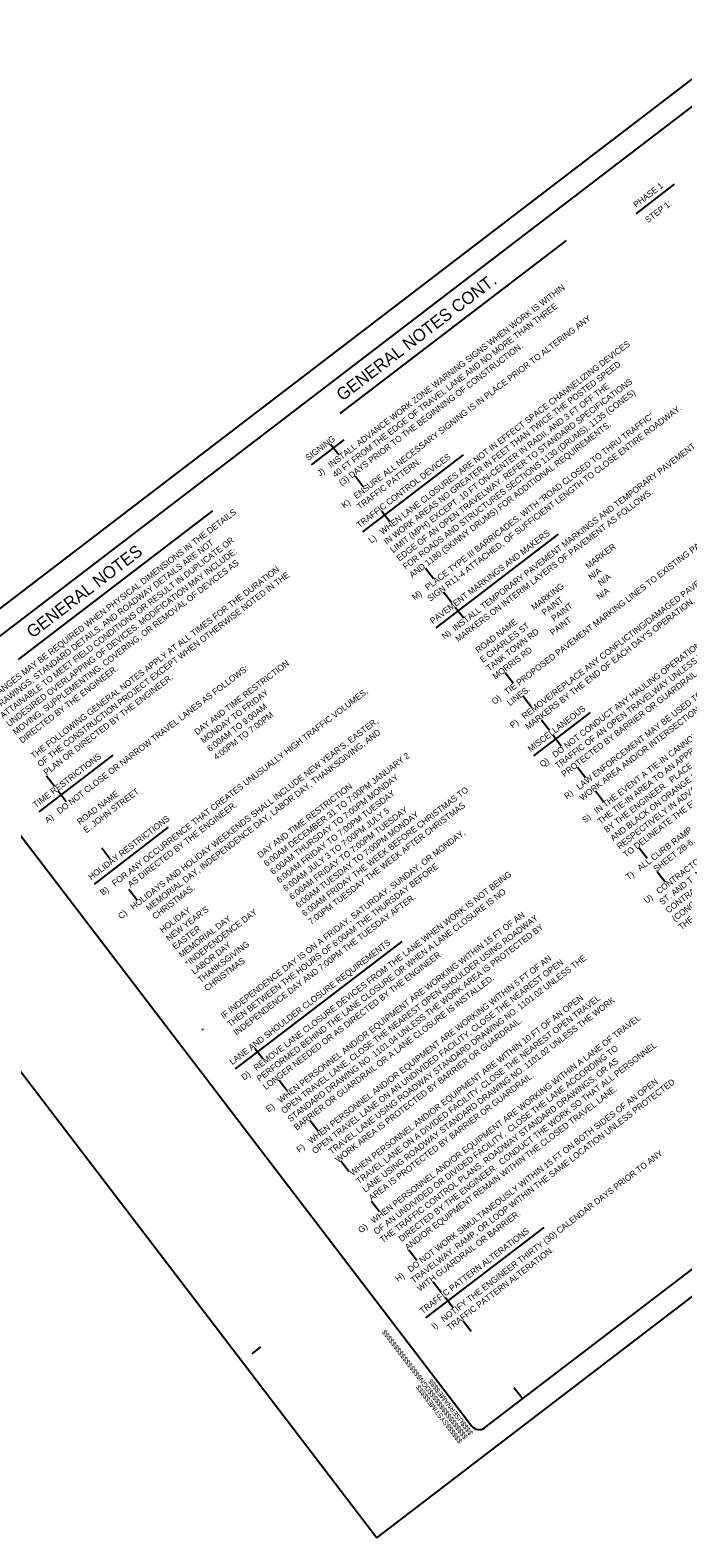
# Model space of a CAD drawing. Extents: x -606 to 2396, y -305 to 3662.
# Drawn here: x 269 to 1012, y 50 to 1764 of the extents above; entities that cross this region are included whole.
import ezdxf

# ---------------------------------------------------------------- set-up
doc = ezdxf.new("R2010")
doc.units = 0
for name, color, linetype in [('DEV BORDER CELL', 7, 'Continuous'), ('DEV TRANSPORTATION OPERATIONS PLAN SHEET', 7, 'Continuous'), ('Scratch_Level_4', 7, 'Continuous'), ('Sheet Plot Border Outside CELL', 7, 'Continuous'), ('Text', 7, 'Continuous')]:
    doc.layers.add(name, color=color, linetype=linetype)

msp = doc.modelspace()

# ---------------------------------------------------------------- linework, layer by layer
at = {"layer": 'DEV BORDER CELL'}
for p, q in [((1323.5, 1908.3), (148.3, 1009.6)), ((621.7, 1328.6), (879.1, 1525.5)), ((256.1, 1049), (476.9, 1217.9)), ((786.1, 175.5), (1961.3, 1074.2)), ((146.4, 995.2), (771.7, 177.5)), ((521.8, 259.8), (531.7, 267.4)), ((777.9, 169.3), (777.9, 169.3))]:
    msp.add_line(p, q, dxfattribs=at)
msp.add_arc((779.9, 183.7), 10.3, 217.404, 307.404, dxfattribs=at)
at = {"layer": 'Scratch_Level_4'}
for p, q in [((610.9, 1293.9), (620.1, 1282)), ((638.8, 1257.6), (647.9, 1245.6)), ((669.3, 1217.6), (678.4, 1205.7)), ((718.8, 1152.9), (727.9, 1141)), ((739.4, 1126), (748.5, 1114.1)), ((752.7, 1108.5), (761.9, 1096.6)), ((809.5, 1034.3), (818.6, 1022.4)), ((830.1, 1007.4), (839.2, 995.5)), ((850.7, 980.4), (859.8, 968.5)), ((864, 963), (873.1, 951)), ((891.8, 926.6), (901, 914.7)), ((287.8, 916.9), (296.9, 905)), ((301.1, 899.5), (310.3, 887.5)), ((912.4, 899.7), (921.5, 887.7)), ((350.7, 834.7), (359.8, 822.8)), ((961.9, 834.9), (971.1, 823)), ((982.5, 808), (991.6, 796.1)), ((381.4, 787.9), (390.5, 776)), ((524.6, 607.2), (533.8, 595.3)), ((552.5, 570.8), (561.6, 558.9)), ((587.5, 525), (596.6, 513)), ((622.6, 479.1), (631.7, 467.2)), ((657.6, 433.3), (666.7, 421.4)), ((699.9, 378), (709, 366.1)), ((727.7, 341.6), (736.8, 329.7)), ((741.1, 324.1), (750.2, 312.2)), ((761.7, 297.2), (770.8, 285.3)), ((819.5, 221.5), (828.7, 209.6))]:
    msp.add_line(p, q, dxfattribs=at)
at = {"layer": 'Sheet Plot Border Outside CELL'}
msp.add_lwpolyline([(663.6, 50.4), (2004.5, 1075.8), (1336.4, 1949.6), (-4.5, 924.2)], close=True, dxfattribs=at)
at = {"layer": 'Text'}
for p, q in [((958.3, 1555.6), (1002.2, 1589.2)), ((589.1, 1270.4), (626.3, 1298.8)), ((647.5, 1194.1), (761.9, 1281.5)), ((730.9, 1084.9), (870.3, 1191.5)), ((842.2, 939.4), (906.6, 988.6)), ((279.4, 875.9), (363.7, 940.4)), ((342.2, 793.7), (426.6, 858.2)), ((502.9, 583.6), (692.3, 728.5)), ((719.3, 300.6), (853.7, 403.3))]:
    msp.add_line(p, q, dxfattribs=at)

# ---------------------------------------------------------------- texts
at = {"layer": 'DEV BORDER CELL'}
for s, p in [('$$$$$$$$$$$$$$$$DGN$$$$$$$$$$$$$$$$', (767.2, 165)), ('$$$$USERNAME$$$$', (773.3, 169.6)), ('$$$$$$SYSTIME$$$$$', (761.2, 160.4))]:
    msp.add_text(s, height=5.584, rotation=127.404, dxfattribs=at).set_placement(p)
at = {"layer": 'DEV TRANSPORTATION OPERATIONS PLAN SHEET'}
for s, p in [('GENERAL NOTES CONT.', (624.3, 1342.2)), ('GENERAL NOTES', (271.8, 1072.6))]:
    msp.add_text(s, height=14, rotation=37.404, dxfattribs=at).set_placement(p)
at = {"layer": 'Text'}
for s, p in [('PHASE 1', (958.6, 1562.3)), ('STEP 1:', (971.9, 1544.9)), ('J)   INSTALL ADVANCE WORK ZONE WARNING SIGNS WHEN WORK IS WITHIN ', (598.9, 1257)), ('     40 FT FROM THE EDGE OF TRAVEL LANE AND NO MORE THAN THREE', (606.1, 1247.6)), ('K)   ENSURE ALL NECESSARY SIGNING IS IN PLACE PRIOR TO ALTERING ANY', (626.7, 1220.6)), ('     (3) DAYS PRIOR TO THE BEGINNING OF CONSTRUCTION.', (613.3, 1238.1)), ('L)   WHEN LANE CLOSURES ARE NOT IN EFFECT SPACE CHANNELIZING DEVICES ', (657.2, 1180.7)), ('     IN WORK AREAS NO GREATER IN FEET THAN TWICE THE POSTED SPEED ', (664.4, 1171.3)), ('     LIMIT (MPH) EXCEPT, 10 FT ON-CENTER IN RADII, AND 3 FT OFF THE ', (671.7, 1161.8)), ('     EDGE OF AN OPEN TRAVELWAY. REFER TO STANDARD SPECIFICATIONS ', (678.9, 1152.4)), ('     FOR ROADS AND STRUCTURES SECTIONS 1130 (DRUMS), 1135 (CONES) ', (686.1, 1142.9)), ('     SIGN R11-4 ATTACHED, OF SUFFICIENT LENGTH TO CLOSE ENTIRE ROADWAY.', (713.9, 1106.5)), ('M)   PLACE TYPE III BARRICADES, WITH "ROAD CLOSED TO THRU TRAFFIC" ', (706.7, 1116)), ('SIGNING', (585.5, 1274.5)), ('     AND 1180 (SKINNY DRUMS) FOR ADDITIONAL REQUIREMENTS.', (693.4, 1133.5)), ('N)  INSTALL TEMPORARY PAVEMENT MARKINGS AND TEMPORARY PAVEMENT ', (740.7, 1071.6)), ('TRAFFIC CONTROL DEVICES', (643.8, 1198.2)), ('     TRAFFIC PATTERN.', (633.9, 1211.2)), ('    MARKERS ON INTERIM LAYERS OF PAVEMENT AS FOLLOWS:', (747.9, 1062.1)), ('CHANGES MAY BE REQUIRED WHEN PHYSICAL DIMENSIONS IN THE DETAILS ', (223.8, 1000.6)), ('O)   TIE PROPOSED PAVEMENT MARKING LINES TO EXISTING PAVEMENT MARKING', (797.4, 997.4)), ('P)   REMOVE/REPLACE ANY CONFLICTING/DAMAGED PAVEMENT MARKINGS AND   ', (818, 970.4)), ('DRAWINGS, STANDARD DETAILS, AND ROADWAY DETAILS ARE NOT ', (231, 991.1)), ('ATTAINABLE TO MEET FIELD CONDITIONS OR RESULT IN DUPLICATE OR ', (238.3, 981.7)), ('PAVEMENT MARKINGS AND MAKERS', (727.3, 1089)), ('UNDESIRED OVERLAPPING OF DEVICES. MODIFICATION MAY INCLUDE: ', (245.5, 972.2)), ('        ROAD NAME         MARKING             MARKER', (762.4, 1043.2)), ('MOVING, SUPPLEMENTING, COVERING, OR REMOVAL OF DEVICES AS ', (252.7, 962.8)), ('THE FOLLOWING GENERAL NOTES APPLY AT ALL TIMES FOR THE DURATION ', (273.3, 935.8)), ('OF THE CONSTRUCTION PROJECT EXCEPT WHEN OTHERWISE NOTED IN THE ', (280.6, 926.4)), ('       E CHARLES ST        PAINT               N/A', (769.6, 1033.8)), ('       TANK TOWN RD        PAINT               N/A', (776.8, 1024.3)), ('Q)   DO NOT CONDUCT ANY HAULING OPERATIONS AGAINST THE FLOW OF', (852, 926)), ('     TRAFFIC OF AN OPEN TRAVELWAY UNLESS THE HAULING OPERATION IS', (859.2, 916.6)), ('     PROTECTED BY BARRIER OR GUARDRAIL OR AS DIRECTED BY THE ENGINEER.', (866.4, 907.1)), ('       MORRIS RD           PAINT               N/A', (784, 1014.9)), ("     MARKERS BY THE END OF EACH DAY'S OPERATION.", (825.2, 961)), ('R)   LAW ENFORCEMENT MAY BE USED TO MAINTAIN TRAFFIC THROUGH THE ', (879.8, 889.7)), ('     WORK AREA AND/OR INTERSECTIONS AS DIRECTED BY THE ENGINEER.', (887, 880.2)), ('     THE TIE-IN AREA TO AN APPROPRIATE ROADWAY ELEVATION AS DETERMINED ', (907.6, 853.3)), ("S)   IN THE EVENT A TIE-IN CANNOT BE MADE IN ONE DAY'S TIME, BRING ", (900.4, 862.7)), ('     BY THE ENGINEER.  PLACE BLACK ON ORANGE "LOOSE GRAVEL" SIGNS (W8-7)', (914.8, 843.8)), ('DAY AND TIME RESTRICTION', (459.2, 962.7)), ('DIRECTED BY THE ENGINEER.', (260, 953.3)), ('PLAN OR DIRECTED BY THE ENGINEER.', (287.8, 916.9)), ('A)   DO NOT CLOSE OR NARROW TRAVEL LANES AS FOLLOWS:', (289.1, 862.5)), ('B)   FOR ANY OCCURRENCE THAT CREATES UNUSUALLY HIGH TRAFFIC VOLUMES,', (351.9, 780.3)), ('MONDAY TO FRIDAY', (466.5, 953.2)), ('     LINES.', (804.6, 987.9)), ("     AND BLACK ON ORANGE ''PAVEMENT ENDS'' SIGNS (W8-3)  AND", (922.1, 834.4)), ('     RESPECTIVELY IN ADVANCE OF THE UNEVEN AREAS. USE DRUMS', (929.3, 824.9)), ('     TO DELINEATE THE EDGE OF ROADWAY ALONG UNPAVED AREAS.', (936.5, 815.5)), ('T)   ALL CURB RAMP LOCATIONS CAN BE FOUND ON THE CURB RAMP TABLE ON ', (949.9, 798)), ('U)   CONTRACTOR SHALL MAINTAIN SOUTHWEST SIDEWALK ACCESS ON E CHARLES', (970.5, 771.1)), ('6:00AM TO 9:00AM', (473.7, 943.8)), ('MISCELLANEOUS', (838.6, 943.5)), ("C)   HOLIDAYS AND HOLIDAY WEEKENDS SHALL INCLUDE NEW YEAR'S, EASTER, ", (372.5, 753.4)), ('4:00PM TO 7:00PM', (480.9, 934.3)), ('     CONTRACTOR SHALL BE RESPONSIBLE TO PROVIDE TEMPORARY SIDEWALKS', (984.9, 752.2)), (' MEMORIAL DAY, INDEPENDENCE DAY, LABOR DAY, THANKSGIVING, AND ', (402, 761)), ('     ST. AND TANK TOWN RD. AT ALL TIMES AS STATED IN THE PHASING.', (977.7, 761.6)), ('     (CONCRETE, ASPHALT, OR OTHER SUITABLE MATERIAL AS APPROVED BY', (992.1, 742.7)), ('6:00AM DECEMBER 31 TO 7:00PM JANUARY 2', (538.2, 813.3)), ('TIME RESTRICTIONS', (275.7, 880)), ('     THE ENGINEER) AT ALL LOCATIONS WHERE THE OPEN PEDESTRIAN', (999.4, 733.2)), ('6:00AM THURSDAY TO 7:00PM MONDAY', (545.4, 803.9)), ('ROAD NAME', (325.8, 860.6)), ('E. JOHN STREET', (333, 851.2)), ('DAY AND TIME RESTRICTION', (531, 822.8)), ('6:00AM FRIDAY TO 7:00PM TUESDAY', (552.7, 794.4)), ('6:00AM FRIDAY THE WEEK BEFORE CHRISTMAS TO ', (581.6, 756.6)), (' AS DIRECTED BY THE ENGINEER.', (381.4, 787.9)), ('6:00AM JULY 3 TO 7:00PM JULY 5', (559.9, 785)), ('6:00AM FRIDAY TO 7:00PM TUESDAY', (567.1, 775.5)), ('6:00AM TUESDAY TO 7:00PM MONDAY', (574.3, 766.1)), ('7:00PM TUESDAY THE WEEK AFTER CHRISTMAS', (588.8, 747.2)), ('HOLIDAY RESTRICTIONS', (338.6, 797.8)), ('IF INDEPENDENCE DAY IS ON A FRIDAY, SATURDAY, SUNDAY, OR MONDAY, ', (489.3, 640.1)), (' SHEET 2B-6.', (979.3, 805.5)), ('THEN BETWEEN THE HOURS OF 6:00AM THE THURSDAY BEFORE', (496.6, 630.7)), ('D)   REMOVE LANE CLOSURE DEVICES FROM THE LANE WHEN WORK IS NOT BEING', (512.6, 570.3)), (' CHRISTMAS.', (409.2, 751.5)), ('INDEPENDENCE DAY AND 7:00PM THE TUESDAY AFTER.', (503.8, 621.2)), ('     PERFORMED BEHIND THE LANE CLOSURE OR WHEN A LANE CLOSURE IS NO', (519.8, 560.8)), ('HOLIDAY', (419.8, 737.7)), ("NEW YEAR'S", (427, 728.3)), ('MEMORIAL DAY', (441.4, 709.4)), ('*INDEPENDENCE DAY', (448.7, 699.9)), ('E)   WHEN PERSONNEL AND/OR EQUIPMENT ARE WORKING WITHIN 15 FT OF AN', (540.4, 533.9)), ('     OPEN TRAVEL LANE, CLOSE THE NEAREST OPEN SHOULDER USING ROADWAY ', (547.6, 524.4)), ('EASTER', (434.2, 718.8)), ('     STANDARD DRAWING NO. 1101.04 UNLESS THE WORK AREA IS PROTECTED BY ', (554.9, 515)), ('LABOR DAY', (455.9, 690.5)), ('THANKSGIVING', (463.1, 681)), ('LANE AND SHOULDER CLOSURE REQUIREMENTS', (499.2, 587.7)), ('CHRISTMAS', (470.4, 671.6)), ('     LONGER NEEDED OR AS DIRECTED BY THE ENGINEER.', (527, 551.4)), ('F)   WHEN PERSONNEL AND/OR EQUIPMENT ARE WORKING WITHIN 5 FT OF AN', (575.4, 488)), ('     OPEN TRAVEL LANE ON AN UNDIVIDED FACILITY, CLOSE THE NEAREST OPEN', (582.7, 478.6)), ('TRAVEL LANE USING ROADWAY STANDARD DRAWING NO. 1101.02 UNLESS THE', (612.1, 486.1)), ('     BARRIER OR GUARDRAIL OR A LANE CLOSURE IS INSTALLED.', (562.1, 505.5)), ('WHEN PERSONNEL AND/OR EQUIPMENT ARE WITHIN 10 FT OF AN OPEN', (635.9, 461.7)), ('TRAVEL LANE ON A DIVIDED FACILITY, CLOSE THE NEAREST OPEN TRAVEL ', (643.2, 452.2)), ('LANE USING ROADWAY STANDARD DRAWING NO. 1101.02 UNLESS THE WORK ', (650.4, 442.7)), ('WORK AREA IS PROTECTED BY BARRIER OR GUARDRAIL.', (619.4, 476.7)), ('G)   WHEN PERSONNEL AND/OR EQUIPMENT ARE WORKING WITHIN A LANE OF TRAVEL', (645.5, 396.4)), ('*', (467.1, 623.1)), ('     OF AN UNDIVIDED OR DIVIDED FACILITY,  CLOSE THE LANE ACCORDING TO', (652.8, 386.9)), (' DIRECTED BY THE ENGINEER.  CONDUCT THE WORK SO THAT ALL PERSONNEL', (689.5, 385)), ('     THE TRAFFIC CONTROL PLANS, ROADWAY STANDARD DRAWINGS, OR AS', (660, 377.5)), ('AREA IS PROTECTED BY BARRIER OR GUARDRAIL.', (657.6, 433.3)), ('H)   DO NOT WORK SIMULTANEOUSLY WITHIN 15 FT ON BOTH SIDES OF AN OPEN ', (687.8, 341.1)), ('     TRAVELWAY, RAMP, OR LOOP WITHIN THE SAME LOCATION UNLESS PROTECTED ', (695.1, 331.6)), (' AND/OR EQUIPMENT REMAIN WITHIN THE CLOSED TRAVEL LANE.', (696.7, 375.6)), ('I)   NOTIFY THE ENGINEER THIRTY (30) CALENDAR DAYS PRIOR TO ANY', (729, 287.2)), ('     WITH GUARDRAIL OR BARRIER.', (702.3, 322.2)), ('TRAFFIC PATTERN ALTERATIONS', (715.6, 304.7)), ('     TRAFFIC PATTERN ALTERATION.', (736.2, 277.8))]:
    msp.add_text(s, height=7, rotation=37.404, dxfattribs=at).set_placement(p)

doc.saveas('drawing.dxf')
